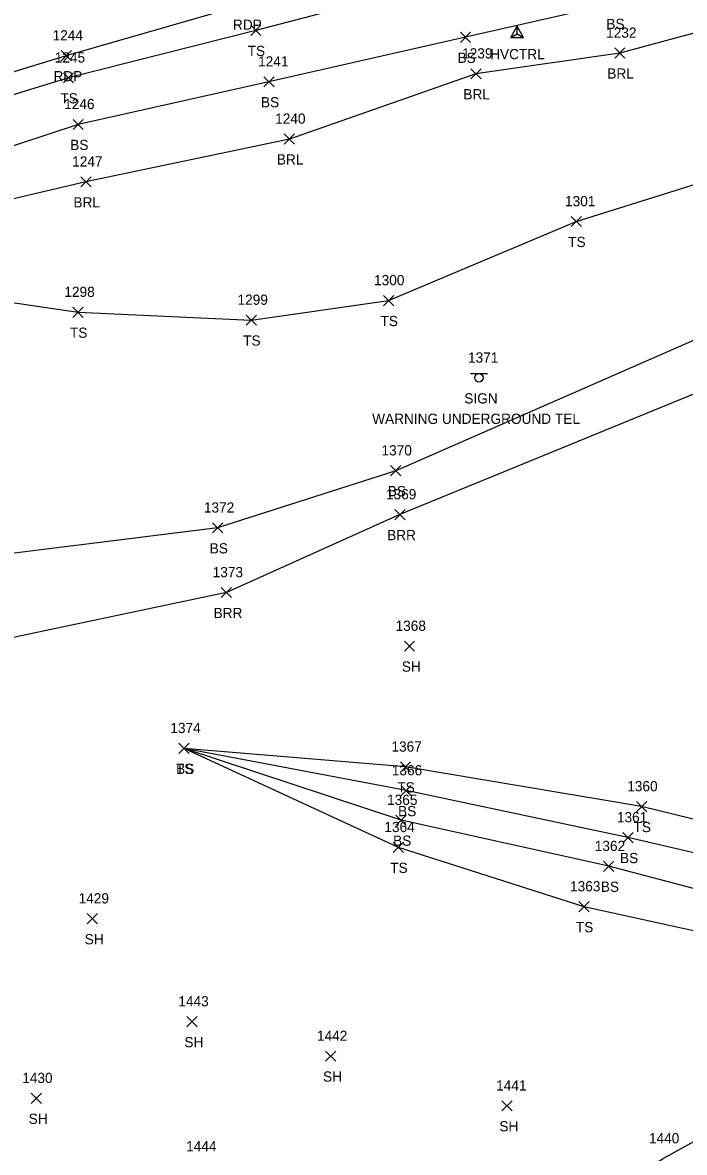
# Model space of a CAD drawing. Extents: x 1599569 to 1610055, y 642560 to 647860.
# Drawn here: x 1602263.8 to 1602393.5, y 647269.5 to 647490.7 of the extents above; entities that cross this region are included whole.
import ezdxf

# ---------------------------------------------------------------- set-up
doc = ezdxf.new("R2010")
doc.units = 0
for name, color, linetype in [('C_A', 7, 'Continuous'), ('CPSM', 7, 'Continuous'), ('L_A', 7, 'Continuous'), ('L_I', 7, 'Continuous'), ('L_TIC', 7, 'Continuous'), ('LABL', 7, 'Continuous'), ('LELB', 7, 'Continuous'), ('LSOGP', 7, 'Continuous'), ('P_A', 7, 'Continuous'), ('P_I', 7, 'Continuous'), ('P_TIC', 7, 'Continuous'), ('PET', 7, 'Continuous'), ('S_A', 7, 'Continuous'), ('S_C', 7, 'Continuous'), ('S_I', 7, 'Continuous'), ('SSGN', 7, 'Continuous')]:
    doc.layers.add(name, color=color, linetype=linetype)

msp = doc.modelspace()

# ---------------------------------------------------------------- linework, layer by layer
at = {"layer": 'CPSM'}
for p, q in [((1602359.49, 647487.82), (1602360.74, 647489.99)), ((1602361.99, 647487.82), (1602360.74, 647489.99)), ((1602360.74, 647488.54), (1602360.74, 647489.99)), ((1602359.49, 647487.82), (1602360.74, 647488.54)), ((1602359.49, 647487.82), (1602361.99, 647487.82)), ((1602360.74, 647488.54), (1602360.74, 647488.54)), ((1602360.74, 647488.54), (1602361.99, 647487.82))]:
    msp.add_line(p, q, dxfattribs=at)
at = {"layer": 'L_TIC'}
for points in [[(1602308.52, 647488.18), (1602310.52, 647490.18)], [(1602310.52, 647488.18), (1602308.52, 647490.18)], [(1602349.6, 647486.83), (1602351.6, 647488.83)], [(1602351.6, 647486.83), (1602349.6, 647488.83)], [(1602379.84, 647483.75), (1602381.84, 647485.75)], [(1602381.84, 647483.75), (1602379.84, 647485.75)], [(1602271.83, 647478.89), (1602273.83, 647480.89)], [(1602273.83, 647478.89), (1602271.83, 647480.89)], [(1602351.64, 647479.69), (1602353.64, 647481.69)], [(1602353.64, 647479.69), (1602351.64, 647481.69)], [(1602311.09, 647478.12), (1602313.09, 647480.12)], [(1602313.09, 647478.12), (1602311.09, 647480.12)], [(1602273.73, 647469.77), (1602275.73, 647471.77)], [(1602275.73, 647469.77), (1602273.73, 647471.77)], [(1602315.1, 647466.92), (1602317.1, 647468.92)], [(1602317.1, 647466.92), (1602315.1, 647468.92)], [(1602275.24, 647458.53), (1602277.24, 647460.53)], [(1602277.24, 647458.53), (1602275.24, 647460.53)], [(1602371.31, 647450.76), (1602373.31, 647452.76)], [(1602373.31, 647450.76), (1602371.31, 647452.76)], [(1602334.54, 647435.29), (1602336.54, 647437.29)], [(1602336.54, 647435.29), (1602334.54, 647437.29)], [(1602273.71, 647433), (1602275.71, 647435)], [(1602275.71, 647433), (1602273.71, 647435)], [(1602307.64, 647431.46), (1602309.64, 647433.46)], [(1602309.64, 647431.46), (1602307.64, 647433.46)], [(1602335.93, 647401.97), (1602337.93, 647403.97)], [(1602337.93, 647401.97), (1602335.93, 647403.97)], [(1602336.77, 647393.37), (1602338.77, 647395.37)], [(1602338.77, 647393.37), (1602336.77, 647395.37)], [(1602301.05, 647390.78), (1602303.05, 647392.78)], [(1602303.05, 647390.78), (1602301.05, 647392.78)], [(1602302.76, 647378.12), (1602304.76, 647380.12)], [(1602304.76, 647378.12), (1602302.76, 647380.12)], [(1602338.64, 647367.62), (1602340.64, 647369.62)], [(1602340.64, 647367.62), (1602338.64, 647369.62)], [(1602294.47, 647347.61), (1602296.47, 647349.61)], [(1602296.47, 647347.61), (1602294.47, 647349.61)], [(1602294.47, 647347.61), (1602296.47, 647349.61)], [(1602296.47, 647347.61), (1602294.47, 647349.61)], [(1602294.47, 647347.61), (1602296.47, 647349.61)], [(1602296.47, 647347.61), (1602294.47, 647349.61)], [(1602294.47, 647347.61), (1602296.47, 647349.61)], [(1602296.47, 647347.61), (1602294.47, 647349.61)], [(1602337.84, 647343.98), (1602339.84, 647345.98)], [(1602339.84, 647343.98), (1602337.84, 647345.98)], [(1602337.96, 647339.33), (1602339.96, 647341.33)], [(1602339.96, 647339.33), (1602337.96, 647341.33)], [(1602384.11, 647336.21), (1602386.11, 647338.21)], [(1602386.11, 647336.21), (1602384.11, 647338.21)], [(1602336.98, 647333.54), (1602338.98, 647335.54)], [(1602338.98, 647333.54), (1602336.98, 647335.54)], [(1602336.45, 647328.22), (1602338.45, 647330.22)], [(1602338.45, 647328.22), (1602336.45, 647330.22)], [(1602381.43, 647330.14), (1602383.43, 647332.14)], [(1602383.43, 647330.14), (1602381.43, 647332.14)], [(1602377.67, 647324.52), (1602379.67, 647326.52)], [(1602379.67, 647324.52), (1602377.67, 647326.52)], [(1602372.82, 647316.61), (1602374.82, 647318.61)], [(1602374.82, 647316.61), (1602372.82, 647318.61)], [(1602276.51, 647314.25), (1602278.51, 647316.25)], [(1602278.51, 647314.25), (1602276.51, 647316.25)], [(1602296.04, 647294.1), (1602298.04, 647296.1)], [(1602298.04, 647294.1), (1602296.04, 647296.1)], [(1602323.2, 647287.35), (1602325.2, 647289.35)], [(1602325.2, 647287.35), (1602323.2, 647289.35)], [(1602265.54, 647279.09), (1602267.54, 647281.09)], [(1602267.54, 647279.09), (1602265.54, 647281.09)], [(1602357.74, 647277.62), (1602359.74, 647279.62)], [(1602359.74, 647277.62), (1602357.74, 647279.62)]]:
    msp.add_lwpolyline(points, dxfattribs=at)
at = {"layer": 'LABL'}
for points in [[(1602538.93, 647499.63), (1602515.77, 647504.47), (1602496.79, 647503.69), (1602468.13, 647504.07), (1602437.38, 647499.25), (1602407.68, 647491.96), (1602380.84, 647484.75), (1602352.64, 647480.69), (1602316.1, 647467.92), (1602276.24, 647459.53), (1602242.61, 647451.62), (1602210.76, 647444.17), (1602175.3, 647438.09), (1602137.9, 647426.83), (1602105.59, 647414.57), (1602070.4, 647404.05), (1602026.56, 647383.89), (1602007.33, 647369.55), (1602002.68, 647344.03), (1602051.38, 647339.86)], [(1602496.95, 647464.06), (1602459.22, 647439.98), (1602411.5, 647424.62), (1602337.77, 647394.37), (1602303.76, 647379.12), (1602250.14, 647367.86), (1602213.09, 647366.56), (1602180.06, 647361.46), (1602139.68, 647347.75), (1602092.2, 647333.52), (1602051.38, 647339.86)]]:
    msp.add_lwpolyline(points, dxfattribs=at)
at = {"layer": 'LELB'}
for points in [[(1602920.15, 647395.93), (1602878.36, 647413), (1602839.66, 647426.29), (1602797.14, 647444.47), (1602757.03, 647458.46), (1602729.83, 647462.67), (1602705.16, 647473.23), (1602676.17, 647483.37), (1602645.06, 647491.74), (1602608.39, 647499.39), (1602581.9, 647503.71), (1602538.18, 647509.07), (1602515.71, 647510.39), (1602496.95, 647511.81), (1602468.81, 647510.52), (1602437.53, 647504.14), (1602407.66, 647504.45), (1602378.45, 647504.43), (1602350.14, 647499.82), (1602309.52, 647489.18), (1602272.83, 647479.89), (1602236.83, 647468.86)], [(1602437.38, 647499.25), (1602407.74, 647500.37), (1602379.76, 647494.45), (1602350.6, 647487.83), (1602312.09, 647479.12), (1602274.73, 647470.77), (1602239.8, 647459.3), (1602209.62, 647450.24), (1602175.3, 647438.09)], [(1601875.37, 647298.23), (1601899.27, 647311.46), (1601933.4, 647328.44), (1601966.96, 647349.6), (1601991.6, 647361.72), (1602007.33, 647369.55), (1602053.05, 647388.73), (1602108.48, 647405.48), (1602138.7, 647415.54), (1602162.27, 647422.58), (1602191.63, 647430.16), (1602222.72, 647436.69), (1602253.77, 647437.09), (1602274.71, 647434), (1602308.64, 647432.46), (1602335.54, 647436.29), (1602372.31, 647451.76), (1602413.17, 647464.59), (1602450.85, 647476.95), (1602485.79, 647485.59)], [(1602495.14, 647473.06), (1602458.34, 647453.1), (1602429.54, 647443.72), (1602409.1, 647434.56), (1602336.93, 647402.97), (1602302.05, 647391.78), (1602247.55, 647384.98), (1602215.85, 647383.22), (1602171.44, 647377.68), (1602139.34, 647373.29), (1602137.15, 647371.2), (1602092.2, 647333.52), (1602059.04, 647322.21), (1602026.95, 647294.33), (1601982.37, 647269.76)], [(1602462.33, 647322.8), (1602430.16, 647326.22), (1602385.11, 647337.21), (1602338.84, 647344.98), (1602295.47, 647348.61)], [(1602460.56, 647316.67), (1602428.69, 647320.37), (1602382.43, 647331.14), (1602338.96, 647340.33), (1602295.47, 647348.61)], [(1602453.66, 647307.87), (1602426.49, 647312.92), (1602378.67, 647325.52), (1602337.98, 647334.54), (1602295.47, 647348.61)], [(1602449.83, 647301.86), (1602424.95, 647306.38), (1602373.82, 647317.61), (1602337.45, 647329.22), (1602295.47, 647348.61)]]:
    msp.add_lwpolyline(points, dxfattribs=at)
at = {"layer": 'LSOGP'}
msp.add_lwpolyline([(1602254.53, 647178.83), (1602291.22, 647199.13), (1602313.63, 647215.92), (1602341.47, 647237.55), (1602366.54, 647253.73), (1602389.31, 647268.29), (1602449.83, 647301.87), (1602453.66, 647307.87), (1602460.55, 647316.67), (1602462.33, 647322.8), (1602472.93, 647343.79), (1602485.85, 647364.3), (1602486.56, 647364.52), (1602487.54, 647364.39), (1602501.5, 647362.17), (1602506.13, 647378.88), (1602530.31, 647430.66), (1602560.99, 647425.29), (1602596.7, 647426.6), (1602638.54, 647420.26), (1602674.58, 647411.62)], dxfattribs=at)
at = {"layer": 'P_TIC'}
for points in [[(1602271.4, 647483.22), (1602273.4, 647485.22)], [(1602273.4, 647483.22), (1602271.4, 647485.22)]]:
    msp.add_lwpolyline(points, dxfattribs=at)
at = {"layer": 'PET'}
msp.add_lwpolyline([(1602921.43, 647398.55), (1602879.84, 647415.39), (1602841.76, 647430.73), (1602798.53, 647448.18), (1602759.07, 647463.24), (1602733.65, 647472.41), (1602708.76, 647480.61), (1602673.93, 647491.11), (1602636.13, 647499.95), (1602599.54, 647506.52), (1602572.66, 647510.09), (1602538.1, 647513.57), (1602515.34, 647514.89), (1602496.48, 647515.72), (1602467.73, 647515.18), (1602434.16, 647513.35), (1602407.64, 647511.45), (1602378.14, 647507.95), (1602349.73, 647503.67), (1602307.56, 647494.3), (1602272.4, 647484.22), (1602235.37, 647472.94)], dxfattribs=at)
at = {"layer": 'SSGN'}
for p, q in [((1602351.59, 647421.99), (1602354.92, 647421.99)), ((1602353.24, 647421.16), (1602353.24, 647421.16))]:
    msp.add_line(p, q, dxfattribs=at)
msp.add_circle((1602353.24, 647421.16), 0.833, dxfattribs=at)

# ---------------------------------------------------------------- texts
at = {"layer": 'C_A'}
msp.add_text('HVCTRL', height=2, dxfattribs=at).set_placement((1602355.43, 647483.54))
at = {"layer": 'L_A'}
for s, p in [('BS', (1602378.2, 647489.45)), ('TS', (1602307.93, 647484.18)), ('BS', (1602349.04, 647482.83)), ('BRL', (1602378.38, 647479.75)), ('TS', (1602271.24, 647474.89)), ('BS', (1602310.53, 647474.12)), ('BRL', (1602350.18, 647475.69)), ('BS', (1602273.17, 647465.77)), ('BRL', (1602313.65, 647462.92)), ('BRL', (1602273.79, 647454.53)), ('TS', (1602370.72, 647446.76)), ('TS', (1602333.95, 647431.29)), ('TS', (1602273.12, 647429)), ('TS', (1602307.05, 647427.46)), ('BS', (1602335.37, 647397.97)), ('BRR', (1602335.25, 647389.37)), ('BS', (1602300.49, 647386.78)), ('BRR', (1602301.25, 647374.12)), ('SH', (1602338.13, 647363.62)), ('TS', (1602293.88, 647343.61)), ('TS', (1602293.88, 647343.61)), ('BS', (1602293.91, 647343.61)), ('BS', (1602293.91, 647343.61)), ('TS', (1602337.25, 647339.98)), ('BS', (1602337.4, 647335.33)), ('TS', (1602383.52, 647332.21)), ('BS', (1602336.42, 647329.54)), ('BS', (1602380.87, 647326.14)), ('TS', (1602335.86, 647324.22)), ('BS', (1602377.11, 647320.52)), ('TS', (1602372.23, 647312.61)), ('SH', (1602276, 647310.25)), ('SH', (1602295.53, 647290.1)), ('SH', (1602322.69, 647283.35)), ('SH', (1602265.03, 647275.09)), ('SH', (1602357.23, 647273.62))]:
    msp.add_text(s, height=2, dxfattribs=at).set_placement(p)
at = {"layer": 'L_I'}
for s, p in [('1232', (1602378.15, 647487.75)), ('1239', (1602349.94, 647483.69)), ('1245', (1602270.14, 647482.89)), ('1241', (1602309.97, 647482.12)), ('1246', (1602271.98, 647473.77)), ('1240', (1602313.32, 647470.92)), ('1247', (1602273.55, 647462.53)), ('1301', (1602370.1, 647454.76)), ('1300', (1602332.69, 647439.29)), ('1298', (1602272.02, 647437)), ('1299', (1602305.94, 647435.46)), ('1370', (1602334.15, 647405.97)), ('1369', (1602335.02, 647397.37)), ('1372', (1602299.35, 647394.78)), ('1373', (1602301.07, 647382.12)), ('1368', (1602336.9, 647371.62)), ('1374', (1602292.78, 647351.61)), ('1374', (1602292.78, 647351.61)), ('1374', (1602292.78, 647351.61)), ('1374', (1602292.78, 647351.61)), ('1367', (1602336.1, 647347.98)), ('1366', (1602336.17, 647343.33)), ('1360', (1602382.29, 647340.21)), ('1365', (1602335.24, 647337.54)), ('1361', (1602380.26, 647334.14)), ('1364', (1602334.71, 647332.22)), ('1362', (1602375.93, 647328.52)), ('1363', (1602371.08, 647320.61)), ('1429', (1602274.81, 647318.25)), ('1443', (1602294.35, 647298.1)), ('1442', (1602321.51, 647291.35)), ('1430', (1602263.76, 647283.09)), ('1441', (1602356.61, 647281.62)), ('1440', (1602386.54, 647271.28)), ('1444', (1602295.88, 647269.72))]:
    msp.add_text(s, height=2, dxfattribs=at).set_placement(p)
at = {"layer": 'P_A'}
for p in [(1602305.05, 647489.3), (1602269.89, 647479.22)]:
    msp.add_text('RDP', height=2, dxfattribs=at).set_placement(p)
at = {"layer": 'P_I'}
msp.add_text('1244', height=2, dxfattribs=at).set_placement((1602269.71, 647487.22))
at = {"layer": 'S_A'}
msp.add_text('SIGN', height=2, dxfattribs=at).set_placement((1602350.37, 647416.14))
at = {"layer": 'S_C'}
msp.add_text('WARNING UNDERGROUND TEL', height=2, dxfattribs=at).set_placement((1602332.32, 647412.14))
at = {"layer": 'S_I'}
msp.add_text('1371', height=2, dxfattribs=at).set_placement((1602351.09, 647424.14))

doc.saveas('drawing.dxf')
